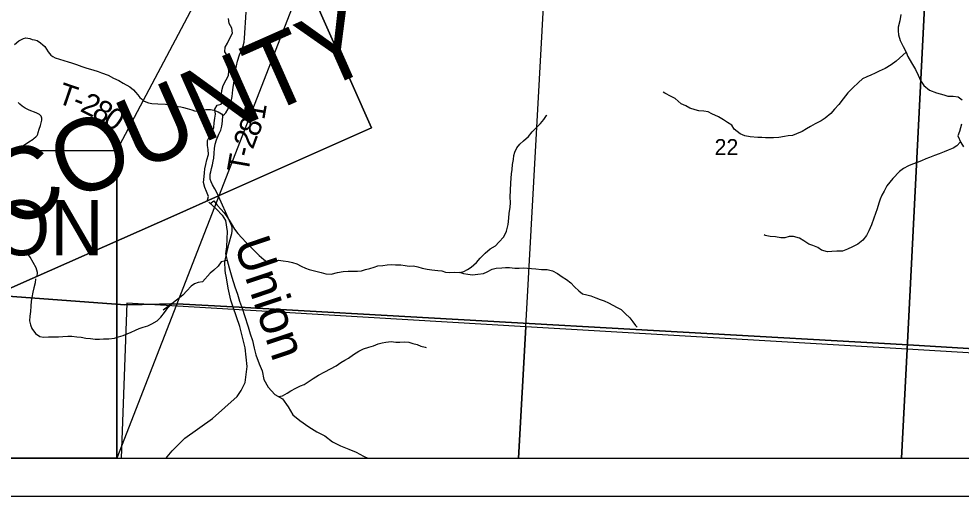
# Model space of a CAD drawing. Extents: x 0 to 34, y 0 to 22.
# Drawn here: x 3.875 to 6.352, y 14 to 15.256 of the extents above; entities that cross this region are included whole.
import ezdxf

# ---------------------------------------------------------------- set-up
doc = ezdxf.new("R2010")
doc.units = 0
for name, color, linetype in [('GM_X_County_Road', 7, 'Continuous'), ('GM_X_County_Text', 7, 'Continuous'), ('GM_X_Minor_River', 7, 'Continuous'), ('GM_X_Minor_River_Text', 7, 'Continuous'), ('GM_X_Section', 7, 'Continuous'), ('GM_X_Section_Text', 7, 'Continuous'), ('GM_X_Township_Road', 7, 'Continuous'), ('GM_X_Township_Road_Text', 7, 'Continuous'), ('GM_X_Unincorporated', 7, 'Continuous'), ('SH_Cut_Line', 7, 'Continuous'), ('SH_Data', 7, 'Continuous'), ('SH_Masking', 7, 'Continuous'), ('SH_Text', 7, 'Continuous')]:
    doc.layers.add(name, color=color, linetype=linetype)

msp = doc.modelspace()

# ---------------------------------------------------------------- linework, layer by layer
at = {"layer": 'GM_X_County_Road'}
for points in [[(4.4192, 14.5817), (4.4173, 14.5934), (4.4165, 14.6162), (4.4267, 14.6627), (4.4345, 14.6908), (4.4352, 14.6969), (4.4354, 14.7072), (4.4332, 14.7146), (4.4286, 14.724), (4.4, 14.7891)], [(4.2621, 14.1), (4.2642, 14.1036), (4.2774, 14.1196), (4.3115, 14.1524), (4.3838, 14.2041), (4.4484, 14.2623), (4.4596, 14.2777), (4.4697, 14.2988), (4.4749, 14.3409), (4.47, 14.3899), (4.4557, 14.4463), (4.4382, 14.4974), (4.4321, 14.5154), (4.4246, 14.5474), (4.4195, 14.5797), (4.4192, 14.5817)]]:
    msp.add_lwpolyline(points, dxfattribs=at)
at = {"layer": 'GM_X_Minor_River'}
for points in [[(6.1936, 15.2666), (6.1909, 15.2507), (6.1867, 15.2333), (6.1867, 15.2238), (6.1879, 15.2132), (6.192, 15.1988), (6.1996, 15.1828), (6.2075, 15.168), (6.2121, 15.1563), (6.2215, 15.14), (6.2325, 15.1222), (6.2396, 15.107), (6.2457, 15.0937), (6.2544, 15.0805), (6.2695, 15.068), (6.2873, 15.0611), (6.3069, 15.0558), (6.3171, 15.0524), (6.3311, 15.0521), (6.3443, 15.0505), (6.3549, 15.0422)], [(4.3695, 14.7753), (4.3734, 14.7878), (4.3681, 14.8018), (4.3637, 14.8117), (4.3603, 14.825), (4.3616, 14.8405), (4.3632, 14.8508), (4.364, 14.861), (4.3659, 14.872), (4.3687, 14.8845), (4.3729, 14.8989), (4.3726, 14.9118), (4.3704, 14.9228), (4.3705, 14.9357), (4.3766, 14.9474), (4.382, 14.9576), (4.3873, 14.9701), (4.3882, 14.9822), (4.3901, 14.9944), (4.3913, 15.0046), (4.3903, 15.0179), (4.396, 15.0281), (4.4066, 15.0314), (4.4112, 15.0424), (4.4079, 15.0568), (4.4084, 15.0671), (4.4122, 15.0799), (4.4195, 15.0947), (4.426, 15.1068), (4.4268, 15.1189), (4.425, 15.1295), (4.4236, 15.144), (4.4244, 15.1565), (4.4165, 15.169), (4.417, 15.1808), (4.4235, 15.1914), (4.4296, 15.205), (4.4365, 15.2178), (4.4351, 15.2311), (4.4276, 15.2437), (4.4258, 15.2566)], [(6.2075, 15.168), (6.1811, 15.1438), (6.1686, 15.1346), (6.1523, 15.1248), (6.1372, 15.1176), (6.1259, 15.113), (6.1149, 15.1077), (6.1047, 15.1031), (6.0933, 15.0974), (6.0828, 15.088), (6.068, 15.0739), (6.054, 15.0606), (6.0419, 15.0455), (6.0306, 15.0303), (6.0192, 15.0182), (6.0098, 15.0064), (5.9947, 14.9939), (5.9845, 14.987), (5.9682, 14.9794), (5.9565, 14.9726), (5.9455, 14.9658), (5.9342, 14.9589), (5.9198, 14.9529), (5.9085, 14.9487), (5.8979, 14.9476), (5.8881, 14.9457), (5.8729, 14.9438), (5.8586, 14.9426), (5.8488, 14.9422), (5.8378, 14.9426), (5.828, 14.9434), (5.8181, 14.943), (5.7977, 14.9452), (5.7834, 14.9475), (5.7709, 14.9532), (5.7554, 14.9657), (5.7493, 14.9755), (5.738, 14.9831), (5.7278, 14.9903), (5.7146, 14.9979), (5.6972, 15.0055), (5.6874, 15.0108), (5.676, 15.0127), (5.6628, 15.0138), (5.653, 15.0165), (5.6386, 15.021), (5.6288, 15.0267), (5.6163, 15.0324), (5.6004, 15.0456), (5.5895, 15.0517), (5.5728, 15.0597), (5.5691, 15.0631)], [(4.3775, 14.7702), (4.3871, 14.7765), (4.3965, 14.7655), (4.4056, 14.7552), (4.4142, 14.745), (4.4214, 14.7354), (4.4274, 14.7259), (4.4357, 14.713), (4.4421, 14.7024), (4.4508, 14.691), (4.4606, 14.6792), (4.472, 14.667), (4.484, 14.6556), (4.4965, 14.6426), (4.5063, 14.6327), (4.5191, 14.6228), (4.532, 14.6129), (4.5452, 14.6174), (4.5577, 14.6208), (4.5695, 14.6192), (4.5827, 14.6169), (4.5944, 14.6146), (4.6054, 14.6111), (4.6167, 14.6046), (4.6281, 14.5993), (4.6379, 14.5958), (4.6591, 14.5912), (4.6693, 14.5885), (4.6818, 14.5847), (4.6958, 14.5843), (4.7128, 14.5884), (4.7276, 14.5913), (4.7405, 14.5917), (4.7647, 14.5916), (4.7753, 14.5923), (4.7859, 14.5964), (4.7976, 14.5991), (4.8086, 14.6024), (4.8185, 14.6062), (4.8321, 14.6069), (4.8427, 14.6088), (4.8544, 14.6091), (4.8646, 14.6087), (4.879, 14.6082), (4.8907, 14.6071), (4.901, 14.6051), (4.9127, 14.6058), (4.9237, 14.6035), (4.9354, 14.5997), (4.9486, 14.5974), (4.9607, 14.5954), (4.9762, 14.5938), (4.9865, 14.5923), (4.9967, 14.5896), (5.0065, 14.5884), (5.0201, 14.5888), (5.033, 14.5887), (5.0447, 14.5913), (5.0546, 14.5958), (5.0644, 14.6019), (5.0781, 14.6147), (5.088, 14.6261), (5.1005, 14.6389), (5.1138, 14.6506), (5.1278, 14.6581), (5.1369, 14.668), (5.1502, 14.6823), (5.1566, 14.6971), (5.1609, 14.7149), (5.1632, 14.7308), (5.1643, 14.7441), (5.1663, 14.7589), (5.1671, 14.7722), (5.1667, 14.7866), (5.1671, 14.8051), (5.1687, 14.823), (5.1695, 14.8366), (5.1703, 14.848), (5.1714, 14.859), (5.1726, 14.8726), (5.1749, 14.8859), (5.1765, 14.8958), (5.1788, 14.9052), (5.1837, 14.9162), (5.1917, 14.926), (5.2019, 14.9343), (5.2148, 14.9464), (5.2247, 14.9582), (5.2353, 14.9691), (5.2467, 14.9801), (5.255, 14.991), (5.2623, 15.0009), (5.2626, 15.0024)], [(6.353, 14.9781), (6.3477, 14.9591), (6.3436, 14.9474), (6.3515, 14.9307), (6.3583, 14.9186)], [(6.3507, 14.9323), (6.3409, 14.9216), (6.3311, 14.9151), (6.3186, 14.9098), (6.308, 14.906), (6.2948, 14.9007), (6.2827, 14.8965), (6.2695, 14.8912), (6.2596, 14.887), (6.2483, 14.8821), (6.2366, 14.8779), (6.2245, 14.873), (6.2139, 14.8688), (6.201, 14.862), (6.1901, 14.8536), (6.1731, 14.8358), (6.1572, 14.8161), (6.1496, 14.802), (6.1439, 14.7918), (6.1394, 14.7816), (6.136, 14.7709), (6.1315, 14.7561), (6.1269, 14.7436), (6.1231, 14.7311), (6.1167, 14.7137), (6.1099, 14.6981), (6.1035, 14.6856), (6.0936, 14.6731), (6.0804, 14.6632), (6.0668, 14.656), (6.0539, 14.6495), (6.0403, 14.6446), (6.0252, 14.6446), (6.0124, 14.6438), (6.001, 14.6427), (5.9855, 14.6472), (5.9757, 14.6541), (5.9625, 14.6597), (5.9523, 14.6628), (5.9383, 14.6719), (5.9273, 14.6787), (5.9114, 14.6828), (5.9005, 14.6832), (5.8884, 14.6798), (5.8786, 14.6798), (5.8638, 14.6824), (5.8506, 14.6828), (5.8374, 14.6855), (5.8341, 14.6874)], [(4.3741, 14.7732), (4.3945, 14.7546), (4.409, 14.7387), (4.4182, 14.7248), (4.4226, 14.6959), (4.4211, 14.6765), (4.4203, 14.656), (4.4176, 14.6373), (4.4221, 14.6195), (4.4273, 14.6008), (4.4345, 14.5757), (4.4427, 14.551), (4.4495, 14.5312), (4.4544, 14.5126), (4.4623, 14.492), (4.4683, 14.4749), (4.4773, 14.4452), (4.4826, 14.4266), (4.4886, 14.4091), (4.4931, 14.3897), (4.498, 14.3718), (4.5063, 14.3483), (4.5142, 14.3296), (4.5186, 14.3072), (4.53, 14.287), (4.5477, 14.2676), (4.5681, 14.2562), (4.5828, 14.2349), (4.5953, 14.2143), (4.6134, 14.1987), (4.6372, 14.1827), (4.6584, 14.1694), (4.6788, 14.1587), (4.6996, 14.1431), (4.7208, 14.1324), (4.7419, 14.124), (4.762, 14.116), (4.7813, 14.105), (4.7924, 14.1)], [(3.9228, 14.5776), (3.9236, 14.588), (3.9203, 14.6009), (3.912, 14.6142), (3.9046, 14.6287), (3.8952, 14.6409)], [(4.4221, 14.6195), (4.4067, 14.6164), (4.3984, 14.6051), (4.3877, 14.5941), (4.3779, 14.5866), (4.3574, 14.5639), (4.3464, 14.562), (4.3369, 14.5583), (4.3275, 14.5522), (4.3165, 14.5405), (4.3055, 14.5284), (4.2765, 14.5055), (4.2763, 14.5073)], [(5.0334, 14.5888), (5.044, 14.586), (5.0549, 14.5837), (5.0678, 14.5821), (5.0814, 14.5836), (5.0962, 14.5858), (5.1064, 14.5903), (5.1189, 14.5975), (5.1299, 14.5994), (5.1443, 14.6008), (5.1541, 14.6015), (5.1651, 14.6011), (5.1791, 14.5999), (5.1905, 14.5999), (5.2018, 14.6002), (5.223, 14.599), (5.234, 14.5978), (5.2491, 14.5966), (5.2635, 14.5958), (5.2779, 14.5931), (5.2907, 14.5855), (5.3032, 14.5767), (5.3149, 14.5702), (5.3258, 14.5615), (5.3353, 14.5504), (5.347, 14.5405), (5.3568, 14.5321), (5.3685, 14.5295), (5.3784, 14.5271), (5.392, 14.5214), (5.4033, 14.5176), (5.4135, 14.5141), (5.4249, 14.5088), (5.4366, 14.5027), (5.4475, 14.4962), (5.4585, 14.4908), (5.4691, 14.4805), (5.4808, 14.4687), (5.4887, 14.4581), (5.4959, 14.4486), (5.5008, 14.4444)], [(3.9185, 14.5714), (3.9177, 14.5615), (3.9139, 14.5483), (3.9112, 14.5365), (3.9085, 14.5229), (3.9069, 14.5126), (3.9061, 14.4994), (3.9053, 14.4857), (3.9038, 14.4732), (3.903, 14.4614), (3.9052, 14.4508), (3.9086, 14.4406), (3.918, 14.4276), (3.9297, 14.4196), (3.9395, 14.4181), (3.9528, 14.4188), (3.9694, 14.4191), (3.9792, 14.4191), (3.9906, 14.4198), (4.0031, 14.4209), (4.0137, 14.4205), (4.0269, 14.419), (4.0386, 14.4186), (4.0511, 14.4159), (4.0628, 14.4147), (4.0753, 14.4131), (4.0863, 14.4127), (4.0972, 14.4135), (4.1116, 14.4142), (4.126, 14.4157), (4.137, 14.4187), (4.1487, 14.4224), (4.1593, 14.4266), (4.1703, 14.4315), (4.1813, 14.4367), (4.1908, 14.4409), (4.2014, 14.4446), (4.2142, 14.4484), (4.2241, 14.4529), (4.2381, 14.4608), (4.2483, 14.4707), (4.2575, 14.4832), (4.2666, 14.4953), (4.2765, 14.5055), (4.2545, 14.4892)], [(4.5578, 14.262), (4.5682, 14.2639), (4.5799, 14.271), (4.5898, 14.2771), (4.6027, 14.2842), (4.6148, 14.2899), (4.6246, 14.294), (4.6353, 14.3004), (4.6482, 14.3091), (4.6622, 14.3185), (4.6792, 14.3272), (4.7088, 14.343), (4.7213, 14.3517), (4.7315, 14.3573), (4.741, 14.363), (4.755, 14.3724), (4.7687, 14.3811), (4.7812, 14.3871), (4.7948, 14.3916), (4.8069, 14.3957), (4.8194, 14.4006), (4.83, 14.4029), (4.8399, 14.4047), (4.8539, 14.4069), (4.8656, 14.4054), (4.8766, 14.4053), (4.8899, 14.4057), (4.8997, 14.4053), (4.911, 14.4014), (4.9216, 14.3991), (4.9315, 14.3949), (4.9428, 14.3918), (4.9454, 14.3914)]]:
    msp.add_lwpolyline(points, dxfattribs=at)
at = {"layer": 'GM_X_Section'}
for points in [[(6.2624, 15.4089), (6.2103, 14.3869), (5.2076, 14.4458), (5.2643, 15.4788)], [(7.27, 15.3432), (7.2187, 14.3265), (6.2103, 14.3869), (6.2624, 15.4089)]]:
    msp.add_lwpolyline(points, close=True, dxfattribs=at)
at = {"layer": 'GM_X_Township_Road'}
for points in [[(4.4, 14.7891), (4.3947, 14.8008), (4.39, 14.8083), (4.3838, 14.8191), (4.3799, 14.8267), (4.3781, 14.834), (4.3775, 14.8402), (4.3779, 14.8473), (4.3793, 14.8534), (4.3815, 14.8619), (4.3835, 14.8714), (4.386, 14.8809), (4.3876, 14.8889), (4.3886, 14.9023), (4.389, 14.9144), (4.391, 14.9259), (4.3943, 14.9371), (4.4007, 14.9518), (4.4054, 14.9627), (4.4082, 14.9736), (4.4098, 14.9864), (4.411, 15.0009), (4.4157, 15.0044), (4.4185, 15.008), (4.4254, 15.0189), (4.4296, 15.0292), (4.4325, 15.0377), (4.4357, 15.0513), (4.4375, 15.069), (4.4408, 15.0923), (4.4442, 15.1196), (4.4466, 15.1321), (4.4496, 15.144), (4.4547, 15.1608), (4.4616, 15.1766), (4.4644, 15.1845), (4.4672, 15.1944), (4.4684, 15.2043), (4.4723, 15.2732)], [(3.8628, 15.1879), (3.8748, 15.1974), (3.8814, 15.2015), (3.8871, 15.2039), (3.8926, 15.2057), (3.8984, 15.2049), (3.9033, 15.2037), (3.9097, 15.2015), (3.9154, 15.2004), (3.9231, 15.1984), (3.9312, 15.1928), (3.938, 15.1875), (3.9431, 15.1824), (3.9477, 15.1756), (3.952, 15.1689), (3.9583, 15.1604), (3.9637, 15.1566), (3.97, 15.1531), (4.004, 15.1426), (4.0132, 15.1396), (4.0258, 15.1354), (4.0399, 15.1305), (4.0535, 15.1256), (4.0688, 15.121), (4.083, 15.1172), (4.0917, 15.1139), (4.1094, 15.1071), (4.1236, 15.0996), (4.1373, 15.0933), (4.1493, 15.0862), (4.1665, 15.0763), (4.1758, 15.0688), (4.1816, 15.0628), (4.1875, 15.0559), (4.1929, 15.049), (4.1972, 15.0448), (4.2026, 15.0399), (4.2087, 15.0369), (4.2154, 15.0349), (4.2247, 15.0331), (4.24, 15.0323), (4.2604, 15.0313), (4.2691, 15.03), (4.2772, 15.0286), (4.2831, 15.0268), (4.2936, 15.0248), (4.3007, 15.024), (4.308, 15.0226), (4.317, 15.0201), (4.3233, 15.0179), (4.3298, 15.0159), (4.3369, 15.0137), (4.3425, 15.0125), (4.3482, 15.0123), (4.3542, 15.0133), (4.3593, 15.0151), (4.3662, 15.0171), (4.373, 15.0175), (4.3789, 15.0171), (4.3872, 15.0149), (4.3985, 15.0106), (4.4074, 15.0054), (4.411, 15.0009)], [(3.8673, 14.909), (3.9008, 14.9318), (3.9124, 14.9393), (3.9152, 14.9421), (3.919, 14.9453), (3.9225, 14.9486), (3.9243, 14.9524), (3.9257, 14.9565), (3.9281, 14.965), (3.9318, 14.9751), (3.935, 14.9894), (3.9354, 14.9943), (3.9334, 14.9999), (3.9291, 15.004), (3.9204, 15.0086), (3.9019, 15.0157), (3.8913, 15.0207), (3.8831, 15.0258), (3.8774, 15.0308), (3.8732, 15.0351)]]:
    msp.add_lwpolyline(points, dxfattribs=at)
at = {"layer": 'GM_X_Township_Road_Text'}
for points in [[(4.1435, 14.1), (5.1881, 14.1), (5.2076, 14.4458), (4.1589, 14.5076)], [(5.1881, 14.1), (6.1957, 14.1), (6.2103, 14.3869), (5.2076, 14.4458)], [(6.1957, 14.1), (7.2077, 14.1), (7.2187, 14.3265), (6.2103, 14.3869)]]:
    msp.add_lwpolyline(points, close=True, dxfattribs=at)
at = {"layer": 'GM_X_Unincorporated'}
for points in [[(2.2853, 20.9), (2.1, 20.9), (2.1, 14.1), (2.8399, 14.1), (2.9778, 14.1609), (3.8099, 14.5285), (4.2904, 14.7408), (4.3998, 14.7897), (4.802, 14.9692), (4.4847, 15.685), (4.2937, 16.1161), (4.0882, 16.6114), (3.972, 16.8916), (3.7367, 17.4136), (3.709, 17.484), (3.4011, 18.2653), (3.1249, 18.9173), (3.0781, 19.0279), (2.9956, 19.2227), (2.9553, 19.318), (2.7473, 19.8121), (2.418, 20.5866)], [(2.8399, 14.1), (7.2132, 14.1), (7.2248, 14.3369), (7.1526, 14.3412), (6.2131, 14.3976), (4.438, 14.498), (4.2897, 14.5063), (4.1531, 14.503), (3.8099, 14.5285), (2.9778, 14.1609)]]:
    msp.add_lwpolyline(points, close=True, dxfattribs=at)
msp.add_lwpolyline([(4.0882, 16.6114), (4.2937, 16.1161), (4.4847, 15.685), (4.802, 14.9692), (4.3998, 14.7897), (4.2904, 14.7408), (3.8099, 14.5285), (4.1531, 14.503), (4.2897, 14.5063), (4.438, 14.498), (6.2131, 14.3976), (7.1526, 14.3412), (7.2248, 14.3369), (7.5073, 14.3182), (7.991, 14.2863), (8.4238, 14.2578), (8.9, 14.2264), (8.9, 20.3234)], dxfattribs=at)
at = {"layer": 'SH_Cut_Line'}
for points in [[(2.1, 20.9), (2.1, 14.1), (2.8399, 14.1), (2.9778, 14.1609), (3.8099, 14.5285), (4.2904, 14.7408), (4.3998, 14.7897), (4.802, 14.9692), (4.4847, 15.685), (4.2937, 16.1161), (4.0882, 16.6114)], [(4.0882, 16.6114), (4.2937, 16.1161), (4.4847, 15.685), (4.802, 14.9692), (4.3998, 14.7897), (4.2904, 14.7408), (3.8099, 14.5285), (2.9778, 14.1609), (2.8399, 14.1), (8.9, 14.1), (8.9, 20.9)]]:
    msp.add_lwpolyline(points, dxfattribs=at)
at = {"layer": 'SH_Data'}
for p, q in [((2.1, 14.1), (8.9, 14.1)), ((2, 14), (9, 14))]:
    msp.add_line(p, q, dxfattribs=at)
at = {"layer": 'SH_Masking'}
msp.add_lwpolyline([(2.1, 14.9089), (4.1319, 14.9089), (4.1319, 14.1), (2.1, 14.1)], close=True, dxfattribs=at)
at = {"layer": 'SH_Text'}
msp.add_lwpolyline([(4.1319, 14.1), (4.1319, 14.9089), (5.3159, 17.1435)], close=True, dxfattribs=at)

# ---------------------------------------------------------------- texts
at = {"layer": 'GM_X_County_Text'}
msp.add_text('SCIOTO COUNTY', height=0.189394, rotation=23.8999, dxfattribs=at).set_placement((2.8904, 14.2774))
at = {"layer": 'GM_X_Minor_River_Text'}
msp.add_text('Union', height=0.09469, rotation=288.4935, dxfattribs=at).set_placement((4.4396, 14.6642))
at = {"layer": 'GM_X_Section_Text'}
msp.add_text('22', height=0.04186, rotation=0, dxfattribs=at).set_placement((5.7041, 14.8974))
at = {"layer": 'GM_X_Township_Road_Text'}
for s, rotation, p in [('T', 341.1029, (3.9729, 15.0353)), ('-', 338.6226, (4.0125, 15.0217)), ('2', 333.8818, (4.0331, 15.0137)), ('8', 328.8662, (4.0633, 14.999)), ('0', 325.3162, (4.0925, 14.9814)), ('1', 80.0746, (4.5198, 14.9882)), ('8', 66.6039, (4.5017, 14.9422)), ('2', 69.7266, (4.4899, 14.9101)), ('-', 75.8606, (4.4846, 14.889)), ('T', 79.9631, (4.4775, 14.8482))]:
    msp.add_text(s, height=0.0568, rotation=rotation, dxfattribs=at).set_placement(p)
at = {"layer": 'SH_Text'}
msp.add_text('BEGIN ACQUISITION', height=0.144931, rotation=360, dxfattribs=at).set_placement((2.1806, 14.6337))

doc.saveas('drawing.dxf')
